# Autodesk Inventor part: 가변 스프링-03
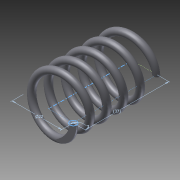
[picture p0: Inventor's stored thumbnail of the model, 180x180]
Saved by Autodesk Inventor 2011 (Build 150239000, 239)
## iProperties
Created: 2015-05
Part Number: 가변 스프링-03
Document SubType Name: Modeling
Designer: Administrator
Density: 7.87 g/cm^3
Material: 탄소강
Mass: 18.8475 g
Surface Area: 32.4803 cm^2
Volume: 2.39485 cm^3
Author: Administrator
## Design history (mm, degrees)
sketch "스케치1"
  geometry: L1 (0, 0)-(11, 0); L2 (11, 0)-(11, 36.411); L3 (11, 36.411)-(0, 36.411); L4 (0, 36.411)-(0, 0); C1 r 1.5 at (11, 0)
  constraints: 8 end point, 2 parallel, 1 centre point, 1 coincident, 1 horizontal, 1 perpendicular
  dimensions: "d0" = 3 diameter of C1; "d1" = 22 diameter of L2 L4; "d2" = 36.4112 distance of L1.end L2.end (derived)
feature "코일1" sketch "스케치1" pitch "d3" = 10; turns "d5" = 5; dims "d4" = 36.4112 (= d2), "d6" = 0, angle "d7" = 90 deg, angle "d8" = 90 deg, "d9" = 0, "d10" = 0
node "작업 평면1"
sketch "스케치2"
  geometry: L1 (0, 0)-(3, 0) reference; 1 further point
  constraints: 1 horizontal alignment
extrude "돌출1" cut sketch "스케치2" distance "d11" = 10; taper "d12" = 0 deg
node "작업 평면2"
sketch "스케치3"
  geometry: L1 (3, 0)-(0, 0) reference; 1 further point
  constraints: 1 horizontal alignment
extrude "돌출2" cut sketch "스케치3" stored distance "d13" = 10; taper "d14" = 0 deg
node "솔리드1"
node "절단 모서리 투영1"
node "절단 모서리 투영2"
